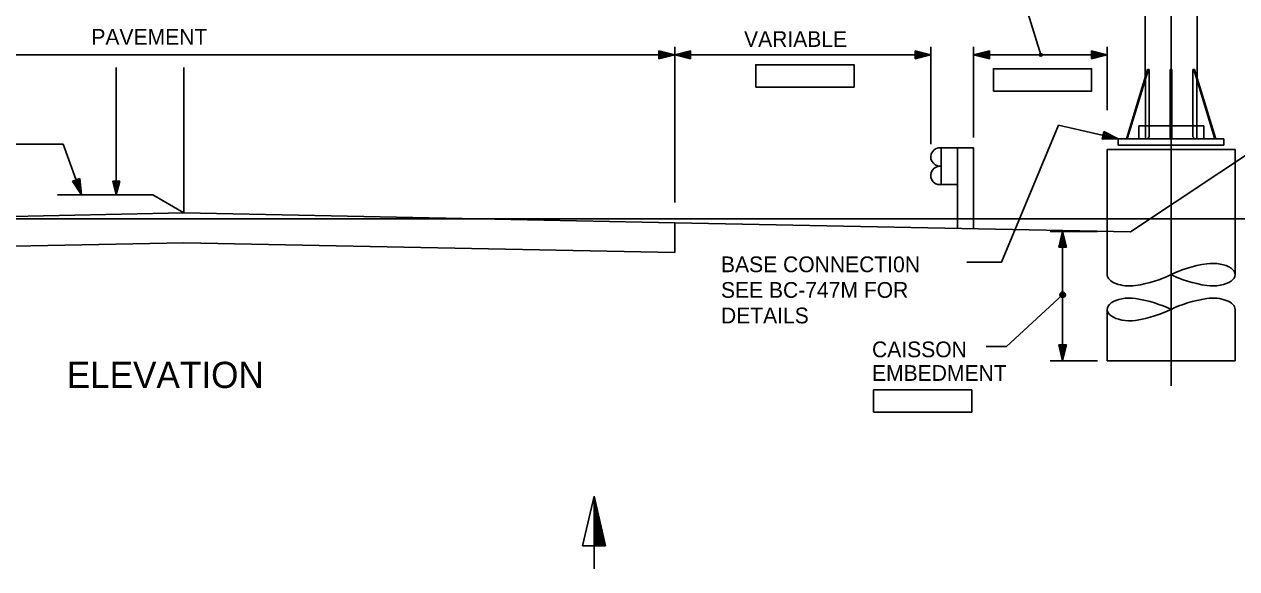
# Model space of a CAD drawing. Extents: x 640117 to 642655, y 297247 to 298435.
# Drawn here: x 641443.9 to 641674.8, y 298131.5 to 298235.3 of the extents above; entities that cross this region are included whole.
import ezdxf

# ---------------------------------------------------------------- set-up
doc = ezdxf.new("R2010")
doc.units = 0
for name, color, linetype in [('10', 7, 'Continuous'), ('2', 7, 'Continuous'), ('25', 7, 'Continuous'), ('46', 7, 'Continuous'), ('47', 7, 'Continuous'), ('50', 7, 'Continuous'), ('51', 7, 'Continuous'), ('52', 7, 'Continuous'), ('53', 7, 'Continuous'), ('55', 7, 'Continuous')]:
    doc.layers.add(name, color=color, linetype=linetype)

msp = doc.modelspace()

# ---------------------------------------------------------------- linework, layer by layer
at = {"layer": '10'}
for p, q in [((641461.47, 298227.08), (641461.47, 298202.79)), ((641454.54, 298205.9), (641453.11, 298205.39)), ((641453.11, 298205.39), (641454.86, 298202.79)), ((641454.39, 298205.66), (641453.39, 298205.3)), ((641453.39, 298205.3), (641454.61, 298203.49)), ((641454.23, 298205.41), (641453.67, 298205.21)), ((641453.67, 298205.21), (641454.35, 298204.18)), ((641453.88, 298205.21), (641454.1, 298204.88)), ((641454.1, 298204.88), (641454.06, 298205.25)), ((641454.35, 298204.18), (641454.23, 298205.41)), ((641454.61, 298203.49), (641454.39, 298205.66)), ((641454.86, 298202.79), (641454.54, 298205.9)), ((641460.81, 298205.43), (641461.47, 298202.79)), ((641462.13, 298205.43), (641460.81, 298205.43)), ((641461.01, 298205.27), (641461.47, 298203.43)), ((641461.93, 298205.27), (641461.01, 298205.27)), ((641461.21, 298205.12), (641461.47, 298204.08)), ((641461.73, 298205.12), (641461.21, 298205.12)), ((641461.39, 298205.06), (641461.47, 298204.72)), ((641461.47, 298202.79), (641462.13, 298205.43)), ((641461.47, 298203.43), (641461.93, 298205.27)), ((641461.47, 298204.08), (641461.73, 298205.12)), ((641461.47, 298204.72), (641461.55, 298205.04))]:
    msp.add_line(p, q, dxfattribs=at)
for points in [[(641454.86, 298202.79), (641451.36, 298212.46), (641428.54, 298212.46)], [(641450.29, 298202.79), (641468.42, 298202.79), (641474.34, 298199.36)]]:
    msp.add_lwpolyline(points, dxfattribs=at)
at = {"layer": '2'}
for points in [[(641583.24, 298223.35), (641601.96, 298223.35), (641601.96, 298227.6), (641583.24, 298227.6)], [(641628.49, 298222.59), (641647.2, 298222.59), (641647.2, 298226.84), (641628.49, 298226.84)], [(641605.66, 298161.38), (641624.37, 298161.38), (641624.37, 298165.63), (641605.66, 298165.63)]]:
    msp.add_lwpolyline(points, close=True, dxfattribs=at)
at = {"layer": '25'}
for p, q in [((641474.34, 298199.36), (641380.87, 298197.49)), ((641474.34, 298199.36), (641567.81, 298197.49)), ((641567.81, 298197.49), (641567.81, 298191.8)), ((641474.34, 298193.67), (641380.87, 298191.8)), ((641474.34, 298193.67), (641567.81, 298191.8))]:
    msp.add_line(p, q, dxfattribs=at)
at = {"layer": '46'}
for p, q in [((641618.55, 298211.79), (641624.73, 298211.79)), ((641618.55, 298204.77), (641618.55, 298211.79)), ((641621.64, 298196.41), (641621.64, 298211.79)), ((641624.73, 298196.35), (641624.73, 298211.79)), ((641618.1, 298204.77), (641621.67, 298204.75))]:
    msp.add_line(p, q, dxfattribs=at)
for centre in [(641618.33, 298210.04), (641618.32, 298206.51)]:
    msp.add_arc(centre, 1.76, 83.0352, 270.4114, dxfattribs=at)
at = {"layer": '47'}
for p, q in [((641654.59, 298195.75), (641711.18, 298233.48)), ((641567.81, 298197.49), (641654.59, 298195.75))]:
    msp.add_line(p, q, dxfattribs=at)
at = {"layer": '50'}
msp.add_line((641662.33, 298166.4), (641662.33, 298363.86), dxfattribs=at)
at = {"layer": '51'}
for p, q in [((641650.14, 298211.48), (641674.52, 298211.48)), ((641650.14, 298195.84), (641650.14, 298211.48)), ((641674.52, 298209.04), (641674.52, 298211.48)), ((641674.52, 298187.6), (641674.52, 298209.04)), ((641650.14, 298187.6), (641650.14, 298195.84)), ((641650.14, 298171.2), (641650.14, 298180.98)), ((641674.52, 298171.2), (641674.52, 298180.98)), ((641650.14, 298171.2), (641674.52, 298171.2))]:
    msp.add_line(p, q, dxfattribs=at)
for centre, major_axis, start_param, end_param in [((641674.52, 298181.51), (17.24, 0), 1.89032, 2.356194), ((641670.2, 298187.6), (4.32, 0), 4.455588, 8.110783), ((641654.46, 298187.6), (-4.32, 0), 0, 1.827597), ((641650.14, 298193.7), (-17.24, 0), 1.89032, 2.356194), ((641674.52, 298193.7), (17.24, 0), 3.926991, 4.392865), ((641654.46, 298180.98), (-4.32, 0), 4.455588, 8.110783), ((641650.14, 298174.88), (-17.24, 0), 3.926991, 4.392865), ((641674.52, 298174.88), (17.24, 0), 1.89032, 2.356194), ((641670.2, 298180.98), (4.32, 0), 0, 1.827597), ((641650.14, 298187.07), (-17.24, 0), 1.89032, 2.356194)]:
    msp.add_ellipse(centre, major_axis=major_axis, ratio=0.5, start_param=start_param, end_param=end_param, dxfattribs=at)
at = {"layer": '52'}
for p, q in [((641567.81, 298229.5), (641564.81, 298230.25)), ((641564.81, 298230.25), (641564.81, 298228.75)), ((641567.07, 298229.5), (641564.98, 298230.02)), ((641564.98, 298230.02), (641564.98, 298228.98)), ((641566.34, 298229.5), (641565.16, 298229.8)), ((641565.16, 298229.8), (641565.16, 298229.21)), ((641567.81, 298201.35), (641567.81, 298231)), ((641570.81, 298230.25), (641567.81, 298229.5)), ((641570.63, 298230.02), (641568.54, 298229.5)), ((641570.45, 298229.8), (641569.27, 298229.5)), ((641570.45, 298229.21), (641570.45, 298229.8)), ((641570.63, 298228.98), (641570.63, 298230.02)), ((641570.81, 298228.75), (641570.81, 298230.25)), ((641616.57, 298229.5), (641613.57, 298230.25)), ((641613.57, 298230.25), (641613.57, 298228.75)), ((641615.84, 298229.5), (641613.75, 298230.02)), ((641613.75, 298230.02), (641613.75, 298228.98)), ((641615.11, 298229.5), (641613.93, 298229.8)), ((641613.93, 298229.8), (641613.93, 298229.21)), ((641616.57, 298212.47), (641616.57, 298231)), ((641624.73, 298213.71), (641624.73, 298231)), ((641627.73, 298230.25), (641624.73, 298229.5)), ((641627.55, 298230.02), (641625.46, 298229.5)), ((641627.37, 298229.8), (641626.2, 298229.5)), ((641627.37, 298229.21), (641627.37, 298229.8)), ((641627.55, 298228.98), (641627.55, 298230.02)), ((641627.73, 298228.75), (641627.73, 298230.25)), ((641650.14, 298229.5), (641647.14, 298230.25)), ((641647.14, 298230.25), (641647.14, 298228.75)), ((641649.4, 298229.5), (641647.31, 298230.02)), ((641647.31, 298230.02), (641647.31, 298228.98)), ((641648.67, 298229.5), (641647.49, 298229.8)), ((641647.49, 298229.8), (641647.49, 298229.21)), ((641650.14, 298218.97), (641650.14, 298231)), ((641298.54, 298229.5), (641616.57, 298229.5)), ((641564.81, 298228.75), (641567.81, 298229.5)), ((641564.98, 298228.98), (641567.07, 298229.5)), ((641565.16, 298229.21), (641566.34, 298229.5)), ((641565.23, 298229.41), (641565.61, 298229.5)), ((641565.61, 298229.5), (641565.25, 298229.59)), ((641567.81, 298229.5), (641570.81, 298228.75)), ((641568.54, 298229.5), (641570.63, 298228.98)), ((641569.27, 298229.5), (641570.45, 298229.21)), ((641570.38, 298229.59), (641570, 298229.5)), ((641570, 298229.5), (641570.36, 298229.41)), ((641613.57, 298228.75), (641616.57, 298229.5)), ((641613.75, 298228.98), (641615.84, 298229.5)), ((641613.93, 298229.21), (641615.11, 298229.5)), ((641614, 298229.41), (641614.38, 298229.5)), ((641614.38, 298229.5), (641614.02, 298229.59)), ((641624.73, 298229.5), (641650.14, 298229.5)), ((641624.73, 298229.5), (641627.73, 298228.75)), ((641625.46, 298229.5), (641627.55, 298228.98)), ((641626.2, 298229.5), (641627.37, 298229.21)), ((641627.3, 298229.59), (641626.93, 298229.5)), ((641626.93, 298229.5), (641627.28, 298229.41)), ((641647.14, 298228.75), (641650.14, 298229.5)), ((641647.31, 298228.98), (641649.4, 298229.5)), ((641647.49, 298229.21), (641648.67, 298229.5)), ((641647.56, 298229.41), (641647.94, 298229.5)), ((641647.94, 298229.5), (641647.58, 298229.59)), ((641474.34, 298227.08), (641474.34, 298199.36)), ((641649.52, 298214.87), (641649.18, 298213.4)), ((641649.64, 298214.6), (641649.4, 298213.59)), ((641649.4, 298213.59), (641651.56, 298213.63)), ((641652.27, 298213.46), (641649.52, 298214.87)), ((641649.76, 298214.34), (641649.63, 298213.77)), ((641649.63, 298213.77), (641650.84, 298213.79)), ((641651.56, 298213.63), (641649.64, 298214.6)), ((641649.74, 298213.95), (641650.13, 298213.95)), ((641650.84, 298213.79), (641649.76, 298214.34)), ((641650.13, 298213.95), (641649.8, 298214.12)), ((641649.18, 298213.4), (641652.27, 298213.46)), ((641302.03, 298198.22), (641718.64, 298198.22)), ((641639.27, 298195.84), (641648.33, 298195.84)), ((641641.68, 298195.84), (641640.93, 298192.84)), ((641641.68, 298195.84), (641641.68, 298171.2)), ((641642.43, 298192.84), (641641.68, 298195.84)), ((641640.93, 298192.84), (641642.43, 298192.84)), ((641641.68, 298195.11), (641641.16, 298193.02)), ((641641.16, 298193.02), (641642.2, 298193.02)), ((641641.68, 298194.38), (641641.39, 298193.2)), ((641641.39, 298193.2), (641641.98, 298193.2)), ((641641.68, 298193.64), (641641.59, 298193.29)), ((641642.2, 298193.02), (641641.68, 298195.11)), ((641641.98, 298193.2), (641641.68, 298194.38)), ((641641.77, 298193.27), (641641.68, 298193.64)), ((641640.93, 298174.2), (641641.68, 298171.2)), ((641642.43, 298174.2), (641640.93, 298174.2)), ((641641.16, 298174.03), (641641.68, 298171.94)), ((641642.2, 298174.03), (641641.16, 298174.03)), ((641641.39, 298173.85), (641641.68, 298172.67)), ((641641.98, 298173.85), (641641.39, 298173.85)), ((641641.59, 298173.78), (641641.68, 298173.4)), ((641641.68, 298171.2), (641642.43, 298174.2)), ((641641.68, 298171.94), (641642.2, 298174.03)), ((641641.68, 298172.67), (641641.98, 298173.85)), ((641641.68, 298173.4), (641641.77, 298173.76)), ((641639.27, 298171.2), (641648.33, 298171.2))]:
    msp.add_line(p, q, dxfattribs=at)
for points in [[(641637.51, 298229.5), (641631.55, 298248.87), (641624.35, 298248.87)], [(641652.27, 298213.46), (641640.91, 298216.08), (641630.05, 298189.99), (641623.46, 298189.99)], [(641641.68, 298183.78), (641630.99, 298173.94), (641627.1, 298173.94)]]:
    msp.add_lwpolyline(points, dxfattribs=at)
for centre, radius in [((641637.51, 298229.5), 0.268), ((641641.68, 298183.78), 0.536), ((641641.68, 298183.78), 0.268)]:
    msp.add_circle(centre, radius, dxfattribs=at)
at = {"layer": '53'}
for p, q in [((641550.26, 298135.91), (641552.44, 298145.37)), ((641554.62, 298135.91), (641552.44, 298145.37)), ((641552.44, 298131.55), (641552.44, 298145.37)), ((641554.62, 298135.91), (641550.26, 298135.91))]:
    msp.add_line(p, q, dxfattribs=at)
msp.add_lwpolyline([(641552.55, 298144.7), (641552.55, 298135.97), (641554.51, 298135.97), (641552.66, 298144.27), (641552.66, 298136.08), (641554.41, 298136.08), (641552.77, 298143.39), (641552.77, 298136.19), (641554.3, 298136.19), (641552.88, 298142.63), (641552.88, 298136.3), (641554.19, 298136.3), (641552.99, 298141.76), (641552.99, 298136.41), (641554.08, 298136.41), (641553.1, 298140.99), (641553.1, 298136.52), (641553.97, 298136.52), (641553.2, 298140.12), (641553.2, 298136.63), (641553.86, 298136.63), (641553.31, 298139.35), (641553.31, 298136.73), (641553.75, 298136.73), (641553.42, 298138.48), (641553.42, 298136.84), (641553.64, 298136.84), (641553.53, 298137.5), (641553.53, 298136.95), (641552.55, 298135.97), (641552.55, 298144.7), (641553.53, 298137.5), (641553.53, 298136.95), (641554.51, 298135.97)], dxfattribs=at)
at = {"layer": '55'}
for p, q in [((641657.38, 298225.12), (641657.38, 298267.48)), ((641667.28, 298225.12), (641667.28, 298267.48)), ((641653.89, 298213.66), (641657.85, 298226.67)), ((641654.05, 298213.66), (641658.01, 298226.67)), ((641657.45, 298213.46), (641657.45, 298225.35)), ((641657.85, 298226.67), (641658.18, 298226.67)), ((641658.18, 298213.87), (641658.18, 298226.67)), ((641662.18, 298226.67), (641662.48, 298226.67)), ((641662.18, 298213.46), (641662.18, 298226.67)), ((641662.48, 298213.46), (641662.48, 298226.67)), ((641666.8, 298226.67), (641666.48, 298226.67)), ((641666.48, 298213.87), (641666.48, 298226.67)), ((641670.61, 298213.66), (641666.65, 298226.67)), ((641670.76, 298213.66), (641666.8, 298226.67)), ((641667.21, 298213.46), (641667.21, 298225.35)), ((641653.89, 298213.46), (641653.89, 298213.66)), ((641653.89, 298213.66), (641654.05, 298213.66)), ((641654.05, 298213.46), (641654.05, 298213.66)), ((641657.83, 298213.46), (641658.18, 298213.87)), ((641666.83, 298213.46), (641666.48, 298213.87)), ((641670.61, 298213.46), (641670.61, 298213.66)), ((641670.76, 298213.66), (641670.61, 298213.66)), ((641670.76, 298213.46), (641670.76, 298213.66)), ((641652.27, 298212.29), (641652.27, 298213.46)), ((641652.27, 298213.46), (641672.39, 298213.46)), ((641652.27, 298212.29), (641672.39, 298212.29)), ((641672.39, 298212.29), (641672.39, 298213.46))]:
    msp.add_line(p, q, dxfattribs=at)
msp.add_lwpolyline([(641656.19, 298215.93), (641656.19, 298213.46), (641668.55, 298213.46), (641668.55, 298215.93)], close=True, dxfattribs=at)

# ---------------------------------------------------------------- texts
at = {"layer": '52'}
for s, p in [('PAVEMENT', (641456.73, 298231.41)), ('VARIABLE', (641581.01, 298231))]:
    msp.add_text(s, height=3, dxfattribs=at).set_placement(p)
at = {"layer": '53'}
for s, height, p in [('BASE CONNECTI0N', 3, (641576.62, 298188.07)), ('SEE BC-747M FOR', 3, (641576.62, 298183.19)), ('DETAILS', 3, (641576.62, 298178.32)), ('CAISSON', 3, (641605.38, 298171.86)), ('ELEVATION', 5, (641452.03, 298166)), ('EMBEDMENT', 3, (641605.38, 298167.36))]:
    msp.add_text(s, height=height, dxfattribs=at).set_placement(p)

doc.saveas('drawing.dxf')
